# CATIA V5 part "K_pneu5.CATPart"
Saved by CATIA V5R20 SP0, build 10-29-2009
Part number: pneu 5
Publications: "rayon pneu", "largeur pneu", "rayon congé", "Plan.+100", "pneu 5"
Bounding box of the stored display mesh (mm): x 100 to 300, y -240 to 240, z -240 to 240
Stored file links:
  G:\Khaled_CFAO_2011\SIL\SIL_GR2\mdardier\Khaled\CAD_ThinkMOTION\K_pneu5.CATPart
  G:\Khaled_CFAO_2011\SIL\SIL_GR2\mdardier\Khaled\CAD_ThinkMOTION\K_ass_tandem.CATProduct
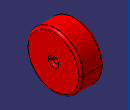
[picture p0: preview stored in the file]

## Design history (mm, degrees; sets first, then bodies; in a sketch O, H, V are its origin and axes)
External parameters (linked from other documents)
  `External.rayon pneu` = 240 mm
  `External.largeur pneu` = 200 mm
  `External.rayon congé` = 20 mm
  `External.demi largeur balancier` = 50 mm
Set1
  Plane1 "Plan.+100": linked copy from another document
  Point1 "pneu 5": linked copy from another document
Body1 (main body)
  Sketch1 on Plane1, origin (100, 0, 0), H (0, 1, 0), V (0, 0, 1)
    circle A1 centre (0, 0) radius 25
    point P1 (0, 0)
    reference projected point E1 (0, 0) from Point1
    circle A2 centre (0, 0) radius 240
    point P2 (0, 0)
    reference projected point E2 (0, 0) from Point1
    radius A2 = 240 {= `External.rayon pneu`}
    radius A1 = 25 {= `External.demi largeur balancier` /2}
    coincidence: P1 E1, P2 E2
  Pad1: profile Sketch1, direction (1, 0, 0), length 200 {= `External.largeur pneu`}
  Fillet1: radius 20 {= `External.rayon congé`}, on end face of Pad1; start face of Pad1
